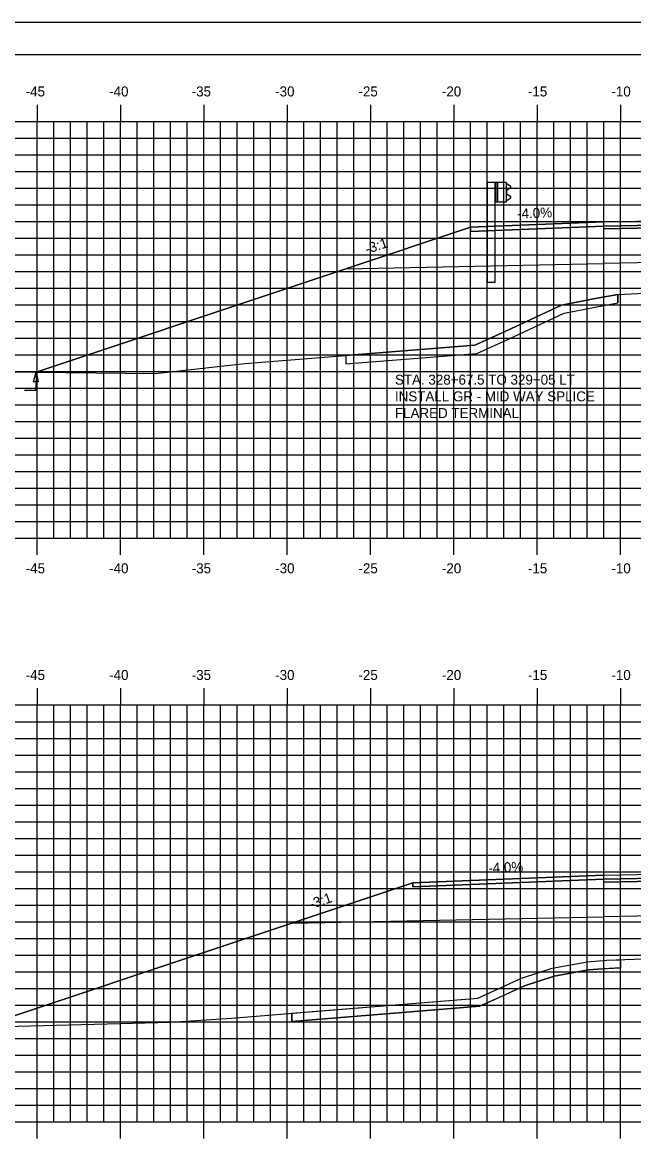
# Model space of a CAD drawing. Extents: x 1140981 to 1141151, y 608981 to 609091.
# Drawn here: x 1141017.9 to 1141054.6, y 609024.1 to 609091.3 of the extents above; entities that cross this region are included whole.
import ezdxf

# ---------------------------------------------------------------- set-up
doc = ezdxf.new("R2010")
doc.units = 0
for name, color, linetype in [('ANNOTATION', 7, 'Continuous'), ('BORDER', 7, 'Continuous'), ('D_Guardrail_Beam_Lt', 7, 'Continuous'), ('D_Roadway_Edge_Shoulder', 7, 'Continuous'), ('D_Roadway_Edge_TW', 7, 'Continuous'), ('D_Roadway_Pavement', 7, 'Continuous'), ('D_Roadway_SlopeLines', 7, 'Continuous'), ('D_Roadway_SubGrade', 7, 'Continuous'), ('D_Text_Standard', 7, 'Continuous'), ('H_V ANNOTATION', 7, 'Continuous'), ('MAJOR', 7, 'Continuous'), ('MINOR', 7, 'Continuous'), ('PLOT BOUNDARY', 7, 'Continuous'), ('S_Roadway_Centerline', 7, 'Continuous'), ('SHADING', 7, 'Continuous')]:
    doc.layers.add(name, color=color, linetype=linetype)

msp = doc.modelspace()

# ---------------------------------------------------------------- linework, layer by layer
for points in [[(1141018.694, 609070.301), (1141034.295, 609075.501), (1141037.295, 609076.501), (1141044.764, 609078.991), (1141044.765, 609078.991), (1141052.758, 609079.311), (1141063.758, 609079.531), (1141074.758, 609079.311), (1141081.758, 609079.031), (1141089.29, 609076.52), (1141092.29, 609075.52), (1141108.295, 609070.185)], [(1141015.324, 609031.014), (1141031.055, 609036.258), (1141034.055, 609037.258), (1141041.302, 609039.673), (1141041.303, 609039.673), (1141052.758, 609040.132), (1141063.758, 609040.352), (1141074.758, 609040.132), (1141081.758, 609039.852), (1141089.29, 609037.341), (1141092.29, 609036.341), (1141104.882, 609032.144)]]:
    msp.add_lwpolyline(points)
at = {"layer": 'BORDER'}
msp.add_lwpolyline([(1140988.758, 608984.335), (1141148.758, 608984.335), (1141148.758, 609089.335), (1140988.758, 609089.335)], close=True, dxfattribs=at)
at = {"layer": 'D_Guardrail_Beam_Lt'}
for p, q in [((1141045.759, 609081.682), (1141045.759, 609075.682)), ((1141046.23, 609081.682), (1141045.759, 609081.682)), ((1141046.917, 609081.682), (1141046.23, 609081.682)), ((1141046.23, 609081.682), (1141046.23, 609080.515)), ((1141046.292, 609081.682), (1141046.292, 609080.515)), ((1141046.396, 609081.682), (1141046.396, 609080.515)), ((1141046.917, 609080.515), (1141046.917, 609081.682)), ((1141046.917, 609081.599), (1141046.991, 609081.584)), ((1141047.15, 609081.334), (1141046.955, 609081.198)), ((1141047.007, 609081.577), (1141047.15, 609081.477)), ((1141046.991, 609080.613), (1141046.917, 609080.599)), ((1141046.921, 609081.134), (1141046.921, 609081.064)), ((1141046.955, 609080.999), (1141047.15, 609080.863)), ((1141047.15, 609080.72), (1141047.007, 609080.62)), ((1141046.23, 609080.515), (1141046.917, 609080.515)), ((1141046.25, 609075.682), (1141046.25, 609080.515)), ((1141046.25, 609075.682), (1141045.759, 609075.682))]:
    msp.add_line(p, q, dxfattribs=at)
for centre, major_axis, start_param, end_param in [((1141046.983, 609081.543), (0.0417, 0), 0.959931, 1.376053), ((1141047.1, 609081.406), (0.0877, 0), 5.323254, 7.243116), ((1141047, 609081.134), (-0.0789, 0), 5.323254, 6.283185), ((1141047, 609081.064), (-0.0789, 0), 6.283185, 7.243116), ((1141046.983, 609080.654), (0.0417, 0), 4.907132, 5.323254), ((1141047.1, 609080.792), (0.0877, 0), 5.323254, 7.243116)]:
    msp.add_ellipse(centre, major_axis=major_axis, ratio=0.995501, start_param=start_param, end_param=end_param, dxfattribs=at)
at = {"layer": 'D_Roadway_Edge_Shoulder'}
for points in [[(1141052.758, 609079.311), (1141044.765, 609078.991), (1141044.765, 609078.741), (1141052.758, 609079.061)], [(1141052.758, 609040.132), (1141041.303, 609039.673), (1141041.303, 609039.423), (1141052.758, 609039.882)]]:
    msp.add_lwpolyline(points, close=True, dxfattribs=at)
at = {"layer": 'D_Roadway_Edge_TW'}
for points in [[(1141052.758, 609079.061), (1141052.758, 609079.311), (1141063.758, 609079.531), (1141074.758, 609079.311), (1141074.758, 609079.061), (1141063.758, 609079.281)], [(1141052.758, 609039.882), (1141052.758, 609040.132), (1141063.758, 609040.352), (1141074.758, 609040.132), (1141074.758, 609039.882), (1141063.758, 609040.102)]]:
    msp.add_lwpolyline(points, close=True, dxfattribs=at)
at = {"layer": 'D_Roadway_Pavement'}
for points in [[(1141052.758, 609078.894), (1141052.758, 609079.061), (1141063.758, 609079.281), (1141074.758, 609079.061), (1141074.758, 609078.894), (1141063.758, 609079.114)], [(1141052.758, 609039.715), (1141052.758, 609039.882), (1141063.758, 609040.102), (1141074.758, 609039.882), (1141074.758, 609039.715), (1141063.758, 609039.935)]]:
    msp.add_lwpolyline(points, close=True, dxfattribs=at)
at = {"layer": 'D_Roadway_SlopeLines'}
for p, q in [((1141053.6, 609074.965), (1141053.6, 609074.465)), ((1141037.295, 609071.298), (1141037.295, 609070.797)), ((1141053.758, 609035.056), (1141053.758, 609034.556)), ((1141034.055, 609031.852), (1141034.055, 609031.358))]:
    msp.add_line(p, q, dxfattribs=at)
for points in [[(1141037.295, 609076.501), (1141034.295, 609075.501)], [(1141034.295, 609075.501), (1141018.694, 609070.301)], [(1141037.295, 609070.797), (1141045.152, 609071.422), (1141047.096, 609072.303), (1141050.392, 609073.834), (1141052.239, 609074.198), (1141053.6, 609074.456)], [(1141034.055, 609037.258), (1141031.055, 609036.258)], [(1141031.055, 609036.258), (1141015.324, 609031.014)], [(1141034.055, 609031.358), (1141045.333, 609032.268), (1141048.014, 609033.489), (1141049.783, 609034.077), (1141051.84, 609034.451), (1141052.959, 609034.533), (1141053.758, 609034.563)]]:
    msp.add_lwpolyline(points, dxfattribs=at)
at = {"layer": 'D_Roadway_SubGrade'}
for points in [[(1141052.758, 609078.894), (1141052.758, 609079.061), (1141044.765, 609078.741), (1141044.765, 609078.991), (1141044.764, 609078.991), (1141037.295, 609076.501), (1141052.758, 609076.811)], [(1141052.758, 609076.811), (1141052.758, 609078.894), (1141063.758, 609079.114), (1141074.758, 609078.894), (1141074.758, 609076.811), (1141063.758, 609077.031)], [(1141052.758, 609039.715), (1141052.758, 609039.882), (1141041.303, 609039.423), (1141041.303, 609039.673), (1141041.302, 609039.673), (1141034.055, 609037.258), (1141052.758, 609037.632)], [(1141052.758, 609037.632), (1141052.758, 609039.715), (1141063.758, 609039.935), (1141074.758, 609039.715), (1141074.758, 609037.632), (1141063.758, 609037.852)]]:
    msp.add_lwpolyline(points, close=True, dxfattribs=at)
at = {"layer": 'D_Text_Standard'}
msp.add_lwpolyline([(1141018.694, 609070.301), (1141018.677, 609069.195), (1141017.997, 609069.195)], dxfattribs=at)
msp.add_lwpolyline([(1141018.694, 609070.301), (1141018.83, 609069.717), (1141018.539, 609069.721)], close=True, dxfattribs=at)
at = {"layer": 'MAJOR'}
for p, q in [((1141018.758, 609086.337), (1141018.758, 609085.335)), ((1141023.758, 609086.337), (1141023.758, 609085.335)), ((1141028.758, 609086.337), (1141028.758, 609085.335)), ((1141033.758, 609086.337), (1141033.758, 609085.335)), ((1141038.758, 609086.337), (1141038.758, 609085.335)), ((1141043.758, 609086.337), (1141043.758, 609085.335)), ((1141048.758, 609086.337), (1141048.758, 609085.335)), ((1141053.758, 609086.337), (1141053.758, 609085.335)), ((1140993.758, 609085.335), (1141133.758, 609085.335)), ((1140993.758, 609085.335), (1141133.758, 609085.335)), ((1141018.758, 609060.335), (1141018.758, 609085.335)), ((1141023.758, 609060.335), (1141023.758, 609085.335)), ((1141028.758, 609060.335), (1141028.758, 609085.335)), ((1141033.758, 609060.335), (1141033.758, 609085.335)), ((1141038.758, 609060.335), (1141038.758, 609085.335)), ((1141043.758, 609060.335), (1141043.758, 609085.335)), ((1141048.758, 609060.335), (1141048.758, 609085.335)), ((1141053.758, 609060.335), (1141053.758, 609085.335)), ((1140993.758, 609080.335), (1141133.758, 609080.335)), ((1140993.758, 609075.335), (1141133.758, 609075.335)), ((1140993.758, 609070.335), (1141133.758, 609070.335)), ((1140993.758, 609065.335), (1141133.758, 609065.335)), ((1140993.758, 609060.335), (1141133.758, 609060.335)), ((1140993.758, 609060.335), (1141133.758, 609060.335)), ((1141018.758, 609059.333), (1141018.758, 609060.335)), ((1141023.758, 609059.333), (1141023.758, 609060.335)), ((1141028.758, 609059.333), (1141028.758, 609060.335)), ((1141033.758, 609059.333), (1141033.758, 609060.335)), ((1141038.758, 609059.333), (1141038.758, 609060.335)), ((1141043.758, 609059.333), (1141043.758, 609060.335)), ((1141048.758, 609059.333), (1141048.758, 609060.335)), ((1141053.758, 609059.333), (1141053.758, 609060.335)), ((1141018.758, 609051.337), (1141018.758, 609050.335)), ((1141023.758, 609051.337), (1141023.758, 609050.335)), ((1141028.758, 609051.337), (1141028.758, 609050.335)), ((1141033.758, 609051.337), (1141033.758, 609050.335)), ((1141038.758, 609051.337), (1141038.758, 609050.335)), ((1141043.758, 609051.337), (1141043.758, 609050.335)), ((1141048.758, 609051.337), (1141048.758, 609050.335)), ((1141053.758, 609051.337), (1141053.758, 609050.335)), ((1140993.758, 609050.335), (1141133.758, 609050.335)), ((1140993.758, 609050.335), (1141133.758, 609050.335)), ((1141018.758, 609025.335), (1141018.758, 609050.335)), ((1141023.758, 609025.335), (1141023.758, 609050.335)), ((1141028.758, 609025.335), (1141028.758, 609050.335)), ((1141033.758, 609025.335), (1141033.758, 609050.335)), ((1141038.758, 609025.335), (1141038.758, 609050.335)), ((1141043.758, 609025.335), (1141043.758, 609050.335)), ((1141048.758, 609025.335), (1141048.758, 609050.335)), ((1141053.758, 609025.335), (1141053.758, 609050.335)), ((1140993.758, 609045.335), (1141133.758, 609045.335)), ((1140993.758, 609040.335), (1141133.758, 609040.335)), ((1140993.758, 609035.335), (1141133.758, 609035.335)), ((1140993.758, 609030.335), (1141133.758, 609030.335)), ((1140993.758, 609025.335), (1141133.758, 609025.335)), ((1140993.758, 609025.335), (1141133.758, 609025.335)), ((1141018.758, 609024.333), (1141018.758, 609025.335)), ((1141023.758, 609024.333), (1141023.758, 609025.335)), ((1141028.758, 609024.333), (1141028.758, 609025.335)), ((1141033.758, 609024.333), (1141033.758, 609025.335)), ((1141038.758, 609024.333), (1141038.758, 609025.335)), ((1141043.758, 609024.333), (1141043.758, 609025.335)), ((1141048.758, 609024.333), (1141048.758, 609025.335)), ((1141053.758, 609024.333), (1141053.758, 609025.335))]:
    msp.add_line(p, q, dxfattribs=at)
at = {"layer": 'MINOR'}
for p, q in [((1141019.758, 609060.335), (1141019.758, 609085.335)), ((1141020.758, 609060.335), (1141020.758, 609085.335)), ((1141021.758, 609060.335), (1141021.758, 609085.335)), ((1141022.758, 609060.335), (1141022.758, 609085.335)), ((1141024.758, 609060.335), (1141024.758, 609085.335)), ((1141025.758, 609060.335), (1141025.758, 609085.335)), ((1141026.758, 609060.335), (1141026.758, 609085.335)), ((1141027.758, 609060.335), (1141027.758, 609085.335)), ((1141029.758, 609060.335), (1141029.758, 609085.335)), ((1141030.758, 609060.335), (1141030.758, 609085.335)), ((1141031.758, 609060.335), (1141031.758, 609085.335)), ((1141032.758, 609060.335), (1141032.758, 609085.335)), ((1141034.758, 609060.335), (1141034.758, 609085.335)), ((1141035.758, 609060.335), (1141035.758, 609085.335)), ((1141036.758, 609060.335), (1141036.758, 609085.335)), ((1141037.758, 609060.335), (1141037.758, 609085.335)), ((1141039.758, 609060.335), (1141039.758, 609085.335)), ((1141040.758, 609060.335), (1141040.758, 609085.335)), ((1141041.758, 609060.335), (1141041.758, 609085.335)), ((1141042.758, 609060.335), (1141042.758, 609085.335)), ((1141044.758, 609060.335), (1141044.758, 609085.335)), ((1141045.758, 609060.335), (1141045.758, 609085.335)), ((1141046.758, 609060.335), (1141046.758, 609085.335)), ((1141047.758, 609060.335), (1141047.758, 609085.335)), ((1141049.758, 609060.335), (1141049.758, 609085.335)), ((1141050.758, 609060.335), (1141050.758, 609085.335)), ((1141051.758, 609060.335), (1141051.758, 609085.335)), ((1141052.758, 609060.335), (1141052.758, 609085.335)), ((1140993.758, 609084.335), (1141133.758, 609084.335)), ((1140993.758, 609083.335), (1141133.758, 609083.335)), ((1140993.758, 609082.335), (1141133.758, 609082.335)), ((1140993.758, 609081.335), (1141133.758, 609081.335)), ((1140993.758, 609079.335), (1141133.758, 609079.335)), ((1140993.758, 609078.335), (1141133.758, 609078.335)), ((1140993.758, 609077.335), (1141133.758, 609077.335)), ((1140993.758, 609076.335), (1141133.758, 609076.335)), ((1140993.758, 609074.335), (1141133.758, 609074.335)), ((1140993.758, 609073.335), (1141133.758, 609073.335)), ((1140993.758, 609072.335), (1141133.758, 609072.335)), ((1140993.758, 609071.335), (1141133.758, 609071.335)), ((1140993.758, 609069.335), (1141133.758, 609069.335)), ((1140993.758, 609068.335), (1141133.758, 609068.335)), ((1140993.758, 609067.335), (1141133.758, 609067.335)), ((1140993.758, 609066.335), (1141133.758, 609066.335)), ((1140993.758, 609064.335), (1141133.758, 609064.335)), ((1140993.758, 609063.335), (1141133.758, 609063.335)), ((1140993.758, 609062.335), (1141133.758, 609062.335)), ((1140993.758, 609061.335), (1141133.758, 609061.335)), ((1141019.758, 609025.335), (1141019.758, 609050.335)), ((1141020.758, 609025.335), (1141020.758, 609050.335)), ((1141021.758, 609025.335), (1141021.758, 609050.335)), ((1141022.758, 609025.335), (1141022.758, 609050.335)), ((1141024.758, 609025.335), (1141024.758, 609050.335)), ((1141025.758, 609025.335), (1141025.758, 609050.335)), ((1141026.758, 609025.335), (1141026.758, 609050.335)), ((1141027.758, 609025.335), (1141027.758, 609050.335)), ((1141029.758, 609025.335), (1141029.758, 609050.335)), ((1141030.758, 609025.335), (1141030.758, 609050.335)), ((1141031.758, 609025.335), (1141031.758, 609050.335)), ((1141032.758, 609025.335), (1141032.758, 609050.335)), ((1141034.758, 609025.335), (1141034.758, 609050.335)), ((1141035.758, 609025.335), (1141035.758, 609050.335)), ((1141036.758, 609025.335), (1141036.758, 609050.335)), ((1141037.758, 609025.335), (1141037.758, 609050.335)), ((1141039.758, 609025.335), (1141039.758, 609050.335)), ((1141040.758, 609025.335), (1141040.758, 609050.335)), ((1141041.758, 609025.335), (1141041.758, 609050.335)), ((1141042.758, 609025.335), (1141042.758, 609050.335)), ((1141044.758, 609025.335), (1141044.758, 609050.335)), ((1141045.758, 609025.335), (1141045.758, 609050.335)), ((1141046.758, 609025.335), (1141046.758, 609050.335)), ((1141047.758, 609025.335), (1141047.758, 609050.335)), ((1141049.758, 609025.335), (1141049.758, 609050.335)), ((1141050.758, 609025.335), (1141050.758, 609050.335)), ((1141051.758, 609025.335), (1141051.758, 609050.335)), ((1141052.758, 609025.335), (1141052.758, 609050.335)), ((1140993.758, 609049.335), (1141133.758, 609049.335)), ((1140993.758, 609048.335), (1141133.758, 609048.335)), ((1140993.758, 609047.335), (1141133.758, 609047.335)), ((1140993.758, 609046.335), (1141133.758, 609046.335)), ((1140993.758, 609044.335), (1141133.758, 609044.335)), ((1140993.758, 609043.335), (1141133.758, 609043.335)), ((1140993.758, 609042.335), (1141133.758, 609042.335)), ((1140993.758, 609041.335), (1141133.758, 609041.335)), ((1140993.758, 609039.335), (1141133.758, 609039.335)), ((1140993.758, 609038.335), (1141133.758, 609038.335)), ((1140993.758, 609037.335), (1141133.758, 609037.335)), ((1140993.758, 609036.335), (1141133.758, 609036.335)), ((1140993.758, 609034.335), (1141133.758, 609034.335)), ((1140993.758, 609033.335), (1141133.758, 609033.335)), ((1140993.758, 609032.335), (1141133.758, 609032.335)), ((1140993.758, 609031.335), (1141133.758, 609031.335)), ((1140993.758, 609029.335), (1141133.758, 609029.335)), ((1140993.758, 609028.335), (1141133.758, 609028.335)), ((1140993.758, 609027.335), (1141133.758, 609027.335)), ((1140993.758, 609026.335), (1141133.758, 609026.335))]:
    msp.add_line(p, q, dxfattribs=at)
at = {"layer": 'PLOT BOUNDARY'}
msp.add_lwpolyline([(1140980.664, 608981.276), (1141150.664, 608981.276), (1141150.664, 609091.276), (1140980.664, 609091.276)], close=True, dxfattribs=at)
at = {"layer": 'S_Roadway_Centerline'}
for points in [[(1140993.758, 609070.235), (1141016.927, 609070.323), (1141025.835, 609070.211), (1141031.23, 609070.816), (1141045.025, 609071.913), (1141046.887, 609072.758), (1141050.236, 609074.313), (1141052.144, 609074.689), (1141053.6, 609074.965), (1141057.959, 609075.178), (1141064.255, 609075.378), (1141069.594, 609075.216), (1141075.604, 609075.039), (1141077.446, 609074.821), (1141079.228, 609074.497), (1141085.647, 609072.383), (1141088.632, 609071.329), (1141093.986, 609070.537), (1141096.999, 609070.318), (1141110.65, 609070.157), (1141115.506, 609070.212)], [(1140993.758, 609030.733), (1141009.977, 609030.874), (1141026.763, 609031.313), (1141030.432, 609031.56), (1141045.208, 609032.752), (1141047.834, 609033.947), (1141049.661, 609034.555), (1141051.778, 609034.94), (1141052.932, 609035.025), (1141057.344, 609035.19), (1141063.779, 609035.507), (1141070.513, 609035.304), (1141074.764, 609035.173), (1141076.322, 609035.016), (1141078.692, 609034.736), (1141083.759, 609032.911), (1141084.999, 609032.561), (1141091.498, 609032.059), (1141093.213, 609032.024), (1141099.245, 609031.951), (1141112.53, 609032.405)]]:
    msp.add_lwpolyline(points, dxfattribs=at)
at = {"layer": 'SHADING'}
for p, q in [((1141053.6, 609074.465), (1141053.6, 609074.965)), ((1141037.295, 609071.298), (1141037.295, 609070.797))]:
    msp.add_line(p, q, dxfattribs=at)
for points in [[(1141053.6, 609074.965), (1141052.144, 609074.689), (1141050.236, 609074.313), (1141046.887, 609072.758), (1141045.025, 609071.913), (1141037.295, 609071.298)], [(1141037.295, 609070.797), (1141045.152, 609071.422), (1141047.096, 609072.303), (1141050.392, 609073.834), (1141052.239, 609074.198), (1141053.6, 609074.465)]]:
    msp.add_lwpolyline(points, dxfattribs=at)
msp.add_lwpolyline([(1141053.758, 609035.056), (1141053.758, 609034.563), (1141052.4, 609034.492), (1141051.84, 609034.451), (1141049.783, 609034.077), (1141048.014, 609033.489), (1141046.673, 609032.878), (1141045.333, 609032.268), (1141034.055, 609031.358), (1141034.055, 609031.852), (1141045.208, 609032.752), (1141047.834, 609033.947), (1141049.661, 609034.555), (1141051.778, 609034.94), (1141052.932, 609035.025)], close=True, dxfattribs=at)

# ---------------------------------------------------------------- texts
at = {"layer": 'ANNOTATION'}
for s, rotation, p in [('-4.0%', 2.29061, (1141047.577, 609079.504)), ('-3:1', 18.43478, (1141038.546, 609077.373)), ('-4.0%', 2.29061, (1141045.846, 609040.256)), ('-3:1', 18.43483, (1141035.196, 609038.092))]:
    msp.add_text(s, height=0.6, rotation=rotation, dxfattribs=at).set_placement(p)
for s, p in [('STA. 328+67.5 TO 329+05 LT', (1141040.234, 609069.549)), ('INSTALL GR - MID WAY SPLICE', (1141040.234, 609068.547)), ('FLARED TERMINAL', (1141040.234, 609067.545))]:
    msp.add_text(s, height=0.6, dxfattribs=at).set_placement(p)
at = {"layer": 'H_V ANNOTATION'}
for s, p in [('-45', (1141018.075, 609086.835)), ('-40', (1141023.083, 609086.835)), ('-35', (1141028.038, 609086.835)), ('-30', (1141033.046, 609086.835)), ('-25', (1141038.043, 609086.835)), ('-20', (1141043.051, 609086.835)), ('-15', (1141048.214, 609086.835)), ('-10', (1141053.222, 609086.835)), ('-45', (1141018.075, 609058.235)), ('-40', (1141023.083, 609058.235)), ('-35', (1141028.038, 609058.235)), ('-30', (1141033.046, 609058.235)), ('-25', (1141038.043, 609058.235)), ('-20', (1141043.051, 609058.235)), ('-15', (1141048.214, 609058.235)), ('-10', (1141053.222, 609058.235)), ('-45', (1141018.075, 609051.835)), ('-40', (1141023.083, 609051.835)), ('-35', (1141028.038, 609051.835)), ('-30', (1141033.046, 609051.835)), ('-25', (1141038.043, 609051.835)), ('-20', (1141043.051, 609051.835)), ('-15', (1141048.214, 609051.835)), ('-10', (1141053.222, 609051.835))]:
    msp.add_text(s, height=0.6, dxfattribs=at).set_placement(p)

doc.saveas('drawing.dxf')
